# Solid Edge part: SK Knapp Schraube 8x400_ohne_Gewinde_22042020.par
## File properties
Author: fknapp
Template: Normal.par
Last saved by: fknapp
Revision: 36
Application: Solid Edge
Username: fknapp
Genauigkeit: 0,99
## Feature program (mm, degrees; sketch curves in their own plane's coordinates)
sketch for "unnamed RevolvedProtrusion 1" plane through (0, 0, 0) normal (1, 0, 0) x-axis (0, 1, 0)
  line (0, 49.2048) -> (7.5, 49.2048)
  arc centre (7.5, 48.7048) radius 0.5 from (7.5, 49.2048) to (7.9949, 48.7762) cw
  line (4, 44.7814) -> (7.9949, 48.7762)
  line (4, 44.7814) -> (4, 39.7814)
  line (4, 39.7814) -> (3, 37.6369)
  line (3, 37.6369) -> (3, 36.5914)
  line (3, 36.5914) -> (4, 36.5914)
  line (4, 36.5914) -> (4, -345.0516)
  line (0, -350.7952) -> (4, -345.0516)
revolve "unnamed RevolvedProtrusion 1" add full turn 360 deg about sketch line (0, 49.2048) -> (0, -350.7952)
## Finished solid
Body 1: solid body, 9 faces, 8 edges, 1 vertex.
  Faces by surface: cone 3, cylinder 3, plane 2, torus 1
  Edges by curve: circle 8
Bounding box of the edges (mm; curved faces can reach further): 15.990 x 15.990 x 394.256, from (-7.9949, -7.9949, -345.0516) to (7.9949, 7.9949, 49.2048).
Cylindrical faces by radius (mm): R3 x1, R4 x2
Conical faces (half-angle, radius in mm at the cone's reference point): 25 deg R4 x1, 34.8543 deg R4 x1, 45 deg R7.9949 x1
Toroidal faces (ring radius, tube radius in mm): R7.5 r0.5 x1
Planar faces by outward normal: +z 2
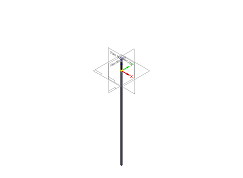
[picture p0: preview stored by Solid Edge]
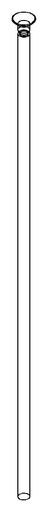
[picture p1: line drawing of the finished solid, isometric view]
